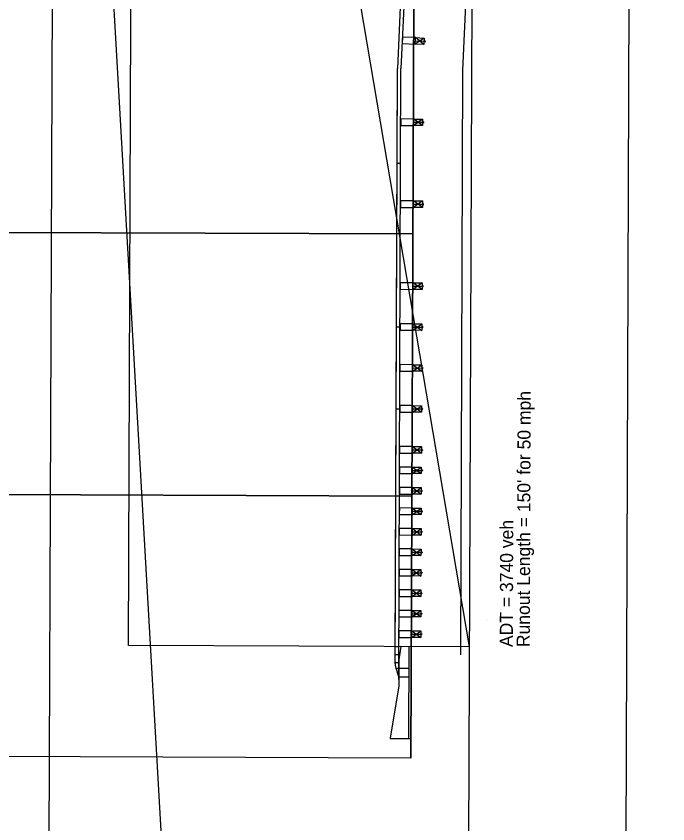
# Model space of a CAD drawing. Extents: x 15359458 to 15360238, y 8797399 to 8799222.
# Drawn here: x 15359925.1 to 15359974.9, y 8798363.3 to 8798425 of the extents above; entities that cross this region are included whole.
import ezdxf

# ---------------------------------------------------------------- set-up
doc = ezdxf.new("R2010")
doc.units = 0
for name, color, linetype in [('_CIVIL_CONSTRUCTION', 7, 'Continuous'), ('Alignment', 7, 'Continuous'), ('MeshTop', 7, 'Continuous'), ('PhoTerrainTriangle', 7, 'Continuous'), ('PhoTerrainVoid', 7, 'Continuous')]:
    doc.layers.add(name, color=color, linetype=linetype)

msp = doc.modelspace()

# ---------------------------------------------------------------- linework, layer by layer
at = {"layer": '_CIVIL_CONSTRUCTION'}
for p, q in [((15359954.472, 8798426.267), (15359954.24, 8798420.983)), ((15359954.742, 8798426.255), (15359954.511, 8798420.98)), ((15359954.616, 8798423.381), (15359954.594, 8798422.881)), ((15359955.616, 8798423.337), (15359954.616, 8798423.381)), ((15359955.594, 8798422.837), (15359955.616, 8798423.337)), ((15359956.282, 8798423.308), (15359955.594, 8798422.837)), ((15359956.26, 8798422.808), (15359955.616, 8798423.337)), ((15359954.594, 8798422.881), (15359955.594, 8798422.837)), ((15359955.605, 8798423.087), (15359956.271, 8798423.058)), ((15359956.368, 8798423.054), (15359956.375, 8798423.053)), ((15359954.213, 8798413.757), (15359954.24, 8798420.983)), ((15359954.484, 8798413.756), (15359954.511, 8798420.98)), ((15359954.497, 8798417.132), (15359954.495, 8798416.631)), ((15359955.498, 8798417.128), (15359954.497, 8798417.132)), ((15359955.496, 8798416.628), (15359955.498, 8798417.128)), ((15359956.164, 8798417.125), (15359955.496, 8798416.628)), ((15359956.162, 8798416.625), (15359955.498, 8798417.128)), ((15359954.495, 8798416.631), (15359955.496, 8798416.628)), ((15359955.497, 8798416.878), (15359956.163, 8798416.875)), ((15359956.26, 8798416.875), (15359956.267, 8798416.875)), ((15359954.069, 8798375.557), (15359954.213, 8798413.757)), ((15359954.213, 8798413.757), (15359954.484, 8798413.756)), ((15359954.213, 8798413.757), (15359954.484, 8798413.756)), ((15359954.335, 8798374.361), (15359954.484, 8798413.756)), ((15359954.473, 8798410.882), (15359954.471, 8798410.381)), ((15359954.471, 8798410.381), (15359955.472, 8798410.378)), ((15359955.474, 8798410.878), (15359954.473, 8798410.882)), ((15359955.472, 8798410.378), (15359955.474, 8798410.878)), ((15359956.141, 8798410.875), (15359955.472, 8798410.378)), ((15359955.473, 8798410.628), (15359956.14, 8798410.625)), ((15359956.139, 8798410.375), (15359955.474, 8798410.878)), ((15359956.237, 8798410.625), (15359956.244, 8798410.625)), ((15359954.449, 8798404.632), (15359954.448, 8798404.131)), ((15359955.45, 8798404.628), (15359954.449, 8798404.632)), ((15359955.448, 8798404.128), (15359955.45, 8798404.628)), ((15359956.117, 8798404.625), (15359955.448, 8798404.128)), ((15359955.449, 8798404.378), (15359956.116, 8798404.375)), ((15359956.115, 8798404.125), (15359955.45, 8798404.628)), ((15359956.213, 8798404.375), (15359956.22, 8798404.375)), ((15359954.448, 8798404.131), (15359955.448, 8798404.128)), ((15359954.069, 8798375.653), (15359954.166, 8798401.257)), ((15359954.166, 8798401.257), (15359954.437, 8798401.256)), ((15359954.438, 8798401.506), (15359954.436, 8798401.007)), ((15359955.437, 8798401.503), (15359954.438, 8798401.506)), ((15359955.435, 8798401.003), (15359955.437, 8798401.503)), ((15359955.435, 8798401.003), (15359956.104, 8798401.5)), ((15359955.436, 8798401.253), (15359956.103, 8798401.25)), ((15359955.437, 8798401.503), (15359956.102, 8798401)), ((15359956.104, 8798401.5), (15359956.102, 8798401)), ((15359956.102, 8798401.17), (15359956.119, 8798401.17)), ((15359956.103, 8798401.33), (15359956.12, 8798401.33)), ((15359956.12, 8798401.33), (15359956.119, 8798401.17)), ((15359956.119, 8798401.29), (15359956.157, 8798401.29)), ((15359956.119, 8798401.274), (15359956.157, 8798401.274)), ((15359956.119, 8798401.226), (15359956.157, 8798401.226)), ((15359956.119, 8798401.21), (15359956.157, 8798401.21)), ((15359956.157, 8798401.29), (15359956.157, 8798401.21)), ((15359956.157, 8798401.26), (15359956.186, 8798401.26)), ((15359956.157, 8798401.24), (15359956.186, 8798401.24)), ((15359956.186, 8798401.26), (15359956.186, 8798401.24)), ((15359954.436, 8798401.007), (15359955.435, 8798401.003)), ((15359954.426, 8798398.381), (15359954.424, 8798397.882)), ((15359955.425, 8798398.378), (15359954.426, 8798398.381)), ((15359955.423, 8798397.878), (15359955.425, 8798398.378)), ((15359955.423, 8798397.878), (15359956.092, 8798398.375)), ((15359955.424, 8798398.128), (15359956.091, 8798398.125)), ((15359955.425, 8798398.378), (15359956.09, 8798397.875)), ((15359956.092, 8798398.375), (15359956.09, 8798397.875)), ((15359956.091, 8798398.205), (15359956.108, 8798398.205)), ((15359956.091, 8798398.045), (15359956.107, 8798398.045)), ((15359956.108, 8798398.205), (15359956.107, 8798398.045)), ((15359956.107, 8798398.101), (15359956.145, 8798398.101)), ((15359956.107, 8798398.085), (15359956.145, 8798398.085)), ((15359956.108, 8798398.165), (15359956.145, 8798398.165)), ((15359956.108, 8798398.149), (15359956.145, 8798398.149)), ((15359956.145, 8798398.165), (15359956.145, 8798398.085)), ((15359956.145, 8798398.135), (15359956.174, 8798398.135)), ((15359956.145, 8798398.115), (15359956.174, 8798398.115)), ((15359956.174, 8798398.135), (15359956.174, 8798398.115)), ((15359954.424, 8798397.882), (15359955.423, 8798397.878)), ((15359954.142, 8798395.008), (15359954.413, 8798395.007)), ((15359954.414, 8798395.257), (15359954.412, 8798394.757)), ((15359955.414, 8798395.253), (15359954.414, 8798395.257)), ((15359955.412, 8798394.753), (15359955.414, 8798395.253)), ((15359955.412, 8798394.753), (15359956.08, 8798395.25)), ((15359955.413, 8798395.003), (15359956.079, 8798395)), ((15359955.414, 8798395.253), (15359956.078, 8798394.75)), ((15359956.08, 8798395.25), (15359956.078, 8798394.75)), ((15359956.079, 8798395.08), (15359956.096, 8798395.08)), ((15359956.079, 8798394.92), (15359956.095, 8798394.92)), ((15359956.096, 8798395.08), (15359956.095, 8798394.92)), ((15359956.096, 8798395.04), (15359956.133, 8798395.04)), ((15359956.096, 8798395.024), (15359956.133, 8798395.024)), ((15359956.096, 8798394.976), (15359956.133, 8798394.976)), ((15359956.096, 8798394.96), (15359956.133, 8798394.96)), ((15359956.133, 8798395.04), (15359956.133, 8798394.96)), ((15359956.133, 8798395.01), (15359956.163, 8798395.01)), ((15359956.133, 8798394.99), (15359956.163, 8798394.99)), ((15359956.163, 8798395.01), (15359956.163, 8798394.99)), ((15359954.412, 8798394.757), (15359955.412, 8798394.753)), ((15359954.402, 8798392.132), (15359954.4, 8798391.632)), ((15359955.402, 8798392.128), (15359954.402, 8798392.132)), ((15359955.4, 8798391.628), (15359955.402, 8798392.128)), ((15359955.4, 8798391.628), (15359956.068, 8798392.125)), ((15359955.401, 8798391.878), (15359956.067, 8798391.875)), ((15359955.402, 8798392.128), (15359956.066, 8798391.625)), ((15359956.068, 8798392.125), (15359956.066, 8798391.625)), ((15359956.068, 8798391.955), (15359956.084, 8798391.955)), ((15359956.084, 8798391.955), (15359956.084, 8798391.795)), ((15359956.084, 8798391.915), (15359956.121, 8798391.915)), ((15359956.084, 8798391.899), (15359956.121, 8798391.899)), ((15359956.084, 8798391.851), (15359956.121, 8798391.851)), ((15359956.084, 8798391.835), (15359956.121, 8798391.835)), ((15359956.121, 8798391.915), (15359956.121, 8798391.835)), ((15359956.121, 8798391.885), (15359956.151, 8798391.885)), ((15359956.121, 8798391.865), (15359956.151, 8798391.865)), ((15359956.151, 8798391.885), (15359956.151, 8798391.865)), ((15359954.4, 8798391.632), (15359955.4, 8798391.628)), ((15359956.067, 8798391.795), (15359956.084, 8798391.795)), ((15359954.396, 8798390.569), (15359954.394, 8798390.069)), ((15359954.394, 8798390.069), (15359955.394, 8798390.066)), ((15359955.396, 8798390.565), (15359954.396, 8798390.569)), ((15359955.394, 8798390.066), (15359955.396, 8798390.565)), ((15359955.394, 8798390.065), (15359956.062, 8798390.563)), ((15359955.395, 8798390.315), (15359956.061, 8798390.313)), ((15359955.396, 8798390.565), (15359956.061, 8798390.063)), ((15359956.062, 8798390.563), (15359956.061, 8798390.063)), ((15359956.061, 8798390.233), (15359956.078, 8798390.233)), ((15359956.062, 8798390.393), (15359956.078, 8798390.393)), ((15359956.078, 8798390.393), (15359956.078, 8798390.233)), ((15359956.078, 8798390.353), (15359956.116, 8798390.353)), ((15359956.078, 8798390.337), (15359956.115, 8798390.337)), ((15359956.078, 8798390.289), (15359956.115, 8798390.289)), ((15359956.078, 8798390.273), (15359956.115, 8798390.273)), ((15359956.116, 8798390.353), (15359956.115, 8798390.273)), ((15359956.115, 8798390.323), (15359956.145, 8798390.322)), ((15359956.115, 8798390.303), (15359956.145, 8798390.302)), ((15359956.145, 8798390.322), (15359956.145, 8798390.302)), ((15359954.39, 8798389.007), (15359954.388, 8798388.507)), ((15359954.39, 8798389.007), (15359954.388, 8798388.507)), ((15359955.39, 8798389.003), (15359954.39, 8798389.007)), ((15359955.39, 8798389.003), (15359954.39, 8798389.007)), ((15359955.388, 8798388.503), (15359955.39, 8798389.003)), ((15359955.388, 8798388.503), (15359955.39, 8798389.003)), ((15359955.388, 8798388.503), (15359956.056, 8798389)), ((15359955.389, 8798388.753), (15359956.056, 8798388.75)), ((15359955.39, 8798389.003), (15359956.055, 8798388.5)), ((15359956.056, 8798389), (15359956.055, 8798388.5)), ((15359956.056, 8798388.83), (15359956.072, 8798388.83)), ((15359956.072, 8798388.83), (15359956.072, 8798388.67)), ((15359956.072, 8798388.79), (15359956.11, 8798388.79)), ((15359956.072, 8798388.774), (15359956.11, 8798388.774)), ((15359956.11, 8798388.79), (15359956.109, 8798388.71)), ((15359956.11, 8798388.76), (15359956.139, 8798388.76)), ((15359956.139, 8798388.76), (15359956.139, 8798388.74)), ((15359954.388, 8798388.507), (15359955.388, 8798388.503)), ((15359954.388, 8798388.507), (15359955.388, 8798388.503)), ((15359956.055, 8798388.67), (15359956.072, 8798388.67)), ((15359956.072, 8798388.726), (15359956.109, 8798388.726)), ((15359956.072, 8798388.71), (15359956.109, 8798388.71)), ((15359956.109, 8798388.74), (15359956.139, 8798388.74)), ((15359954.384, 8798387.444), (15359954.383, 8798386.944)), ((15359954.383, 8798386.944), (15359955.382, 8798386.941)), ((15359955.384, 8798387.44), (15359954.384, 8798387.444)), ((15359955.382, 8798386.941), (15359955.384, 8798387.44)), ((15359955.382, 8798386.94), (15359956.051, 8798387.438)), ((15359955.383, 8798387.19), (15359956.05, 8798387.188)), ((15359955.384, 8798387.44), (15359956.049, 8798386.938)), ((15359956.051, 8798387.438), (15359956.049, 8798386.938)), ((15359956.049, 8798387.108), (15359956.066, 8798387.108)), ((15359956.05, 8798387.268), (15359956.066, 8798387.268)), ((15359956.066, 8798387.268), (15359956.066, 8798387.108)), ((15359956.066, 8798387.228), (15359956.104, 8798387.228)), ((15359956.066, 8798387.212), (15359956.104, 8798387.212)), ((15359956.066, 8798387.164), (15359956.103, 8798387.164)), ((15359956.066, 8798387.148), (15359956.103, 8798387.148)), ((15359956.104, 8798387.228), (15359956.103, 8798387.148)), ((15359956.104, 8798387.198), (15359956.133, 8798387.197)), ((15359956.104, 8798387.178), (15359956.133, 8798387.177)), ((15359956.133, 8798387.197), (15359956.133, 8798387.177)), ((15359954.379, 8798385.882), (15359954.377, 8798385.382)), ((15359955.378, 8798385.878), (15359954.379, 8798385.882)), ((15359955.376, 8798385.378), (15359955.378, 8798385.878)), ((15359955.376, 8798385.378), (15359956.045, 8798385.875)), ((15359955.378, 8798385.878), (15359956.043, 8798385.375)), ((15359956.045, 8798385.875), (15359956.043, 8798385.375)), ((15359956.044, 8798385.705), (15359956.061, 8798385.705)), ((15359956.061, 8798385.705), (15359956.06, 8798385.545)), ((15359954.377, 8798385.382), (15359955.376, 8798385.378)), ((15359955.377, 8798385.628), (15359956.044, 8798385.625)), ((15359956.043, 8798385.545), (15359956.06, 8798385.545)), ((15359956.06, 8798385.665), (15359956.098, 8798385.665)), ((15359956.06, 8798385.649), (15359956.098, 8798385.649)), ((15359956.06, 8798385.601), (15359956.098, 8798385.601)), ((15359956.06, 8798385.585), (15359956.098, 8798385.585)), ((15359956.098, 8798385.665), (15359956.098, 8798385.585)), ((15359956.098, 8798385.635), (15359956.127, 8798385.635)), ((15359956.098, 8798385.615), (15359956.127, 8798385.615)), ((15359956.127, 8798385.635), (15359956.127, 8798385.615)), ((15359954.373, 8798384.319), (15359954.371, 8798383.819)), ((15359955.372, 8798384.315), (15359954.373, 8798384.319)), ((15359955.37, 8798383.816), (15359955.372, 8798384.315)), ((15359955.37, 8798383.815), (15359956.039, 8798384.313)), ((15359955.371, 8798384.065), (15359956.038, 8798384.063)), ((15359955.372, 8798384.315), (15359956.037, 8798383.813)), ((15359956.039, 8798384.313), (15359956.037, 8798383.813)), ((15359956.038, 8798384.143), (15359956.055, 8798384.143)), ((15359956.038, 8798383.983), (15359956.054, 8798383.983)), ((15359956.055, 8798384.143), (15359956.054, 8798383.983)), ((15359956.054, 8798384.087), (15359956.092, 8798384.087)), ((15359956.054, 8798384.039), (15359956.092, 8798384.039)), ((15359956.054, 8798384.023), (15359956.092, 8798384.023)), ((15359956.055, 8798384.103), (15359956.092, 8798384.103)), ((15359956.092, 8798384.103), (15359956.092, 8798384.023)), ((15359956.092, 8798384.073), (15359956.121, 8798384.072)), ((15359956.092, 8798384.053), (15359956.121, 8798384.052)), ((15359956.121, 8798384.072), (15359956.121, 8798384.052)), ((15359954.371, 8798383.819), (15359955.37, 8798383.816)), ((15359954.367, 8798382.757), (15359954.365, 8798382.257)), ((15359955.366, 8798382.753), (15359954.367, 8798382.757)), ((15359955.364, 8798382.253), (15359955.366, 8798382.753)), ((15359955.364, 8798382.253), (15359956.033, 8798382.75)), ((15359955.366, 8798382.753), (15359956.031, 8798382.25)), ((15359956.033, 8798382.75), (15359956.031, 8798382.25)), ((15359954.365, 8798382.257), (15359955.364, 8798382.253)), ((15359955.365, 8798382.503), (15359956.032, 8798382.5)), ((15359956.032, 8798382.58), (15359956.049, 8798382.58)), ((15359956.032, 8798382.42), (15359956.048, 8798382.42)), ((15359956.049, 8798382.58), (15359956.048, 8798382.42)), ((15359956.048, 8798382.476), (15359956.086, 8798382.476)), ((15359956.048, 8798382.46), (15359956.086, 8798382.46)), ((15359956.049, 8798382.54), (15359956.086, 8798382.54)), ((15359956.049, 8798382.524), (15359956.086, 8798382.524)), ((15359956.086, 8798382.54), (15359956.086, 8798382.46)), ((15359956.086, 8798382.51), (15359956.115, 8798382.51)), ((15359956.086, 8798382.49), (15359956.115, 8798382.49)), ((15359956.115, 8798382.51), (15359956.115, 8798382.49)), ((15359954.361, 8798381.194), (15359954.359, 8798380.694)), ((15359955.36, 8798381.19), (15359954.361, 8798381.194)), ((15359955.358, 8798380.691), (15359955.36, 8798381.19)), ((15359955.358, 8798380.69), (15359956.027, 8798381.188)), ((15359955.359, 8798380.94), (15359956.026, 8798380.938)), ((15359955.36, 8798381.19), (15359956.025, 8798380.688)), ((15359956.027, 8798381.188), (15359956.025, 8798380.688)), ((15359956.026, 8798381.018), (15359956.043, 8798381.018)), ((15359956.026, 8798380.858), (15359956.042, 8798380.858)), ((15359956.043, 8798381.018), (15359956.042, 8798380.858)), ((15359956.042, 8798380.914), (15359956.08, 8798380.914)), ((15359956.042, 8798380.898), (15359956.08, 8798380.898)), ((15359956.043, 8798380.978), (15359956.08, 8798380.978)), ((15359956.043, 8798380.962), (15359956.08, 8798380.962)), ((15359956.08, 8798380.978), (15359956.08, 8798380.898)), ((15359956.08, 8798380.948), (15359956.109, 8798380.948)), ((15359956.08, 8798380.928), (15359956.109, 8798380.928)), ((15359956.109, 8798380.948), (15359956.109, 8798380.928)), ((15359954.359, 8798380.694), (15359955.358, 8798380.691)), ((15359954.355, 8798379.632), (15359954.353, 8798379.132)), ((15359955.354, 8798379.628), (15359954.355, 8798379.632)), ((15359955.353, 8798379.128), (15359955.354, 8798379.628)), ((15359955.353, 8798379.128), (15359956.021, 8798379.625)), ((15359955.354, 8798379.628), (15359956.019, 8798379.125)), ((15359956.021, 8798379.625), (15359956.019, 8798379.125)), ((15359954.353, 8798379.132), (15359955.353, 8798379.128)), ((15359955.353, 8798379.378), (15359956.02, 8798379.375)), ((15359956.02, 8798379.455), (15359956.037, 8798379.455)), ((15359956.02, 8798379.295), (15359956.036, 8798379.295)), ((15359956.037, 8798379.455), (15359956.036, 8798379.295)), ((15359956.036, 8798379.335), (15359956.074, 8798379.335)), ((15359956.037, 8798379.415), (15359956.074, 8798379.415)), ((15359956.037, 8798379.399), (15359956.074, 8798379.399)), ((15359956.037, 8798379.351), (15359956.074, 8798379.351)), ((15359956.074, 8798379.415), (15359956.074, 8798379.335)), ((15359956.074, 8798379.385), (15359956.104, 8798379.385)), ((15359956.074, 8798379.365), (15359956.103, 8798379.365)), ((15359956.104, 8798379.385), (15359956.103, 8798379.365)), ((15359954.349, 8798378.069), (15359954.347, 8798377.569)), ((15359955.349, 8798378.065), (15359954.349, 8798378.069)), ((15359955.347, 8798377.566), (15359955.349, 8798378.065)), ((15359955.347, 8798377.565), (15359956.015, 8798378.063)), ((15359955.348, 8798377.815), (15359956.014, 8798377.813)), ((15359955.349, 8798378.065), (15359956.013, 8798377.563)), ((15359956.015, 8798378.063), (15359956.013, 8798377.563)), ((15359956.014, 8798377.893), (15359956.031, 8798377.893)), ((15359956.014, 8798377.733), (15359956.03, 8798377.733)), ((15359956.031, 8798377.893), (15359956.03, 8798377.733)), ((15359956.031, 8798377.853), (15359956.068, 8798377.853)), ((15359956.031, 8798377.837), (15359956.068, 8798377.837)), ((15359956.031, 8798377.789), (15359956.068, 8798377.789)), ((15359956.031, 8798377.773), (15359956.068, 8798377.773)), ((15359956.068, 8798377.853), (15359956.068, 8798377.773)), ((15359956.068, 8798377.823), (15359956.098, 8798377.823)), ((15359956.068, 8798377.803), (15359956.098, 8798377.803)), ((15359956.098, 8798377.823), (15359956.098, 8798377.803)), ((15359954.347, 8798377.569), (15359955.347, 8798377.566)), ((15359954.074, 8798376.862), (15359954.344, 8798376.861)), ((15359954.511, 8798376.86), (15359954.341, 8798375.861)), ((15359955.303, 8798376.857), (15359954.511, 8798376.86)), ((15359955.11, 8798369.858), (15359955.136, 8798376.858)), ((15359955.276, 8798369.857), (15359955.303, 8798376.857)), ((15359954.071, 8798376.258), (15359954.342, 8798376.257)), ((15359954.341, 8798375.861), (15359954.333, 8798373.863)), ((15359954.069, 8798375.653), (15359954.34, 8798375.652)), ((15359955.13, 8798375.191), (15359954.127, 8798375.195)), ((15359954.16, 8798375.095), (15359954.215, 8798374.952)), ((15359954.31, 8798374.611), (15359954.309, 8798374.361)), ((15359955.127, 8798374.525), (15359954.309, 8798374.528)), ((15359954.335, 8798374.361), (15359954.309, 8798374.361)), ((15359954.333, 8798373.863), (15359953.693, 8798369.867)), ((15359953.693, 8798369.867), (15359953.693, 8798369.863)), ((15359953.693, 8798369.863), (15359955.276, 8798369.857))]:
    msp.add_line(p, q, dxfattribs=at)
for points in [[(15359955.594, 8798422.837), (15359955.616, 8798423.337), (15359956.282, 8798423.308), (15359956.26, 8798422.808)], [(15359955.496, 8798416.628), (15359955.498, 8798417.128), (15359956.164, 8798417.125), (15359956.162, 8798416.625)], [(15359955.472, 8798410.378), (15359955.474, 8798410.878), (15359956.141, 8798410.875), (15359956.139, 8798410.375)], [(15359955.448, 8798404.128), (15359955.45, 8798404.628), (15359956.117, 8798404.625), (15359956.115, 8798404.125)], [(15359955.435, 8798401.003), (15359955.437, 8798401.503), (15359956.104, 8798401.5), (15359956.102, 8798401)], [(15359955.423, 8798397.878), (15359955.425, 8798398.378), (15359956.092, 8798398.375), (15359956.09, 8798397.875)], [(15359955.412, 8798394.753), (15359955.414, 8798395.253), (15359956.08, 8798395.25), (15359956.078, 8798394.75)], [(15359955.4, 8798391.628), (15359955.402, 8798392.128), (15359956.068, 8798392.125), (15359956.066, 8798391.625)], [(15359955.394, 8798390.065), (15359955.396, 8798390.565), (15359956.062, 8798390.563), (15359956.061, 8798390.063)], [(15359955.388, 8798388.503), (15359955.39, 8798389.003), (15359956.056, 8798389), (15359956.055, 8798388.5)], [(15359955.382, 8798386.94), (15359955.384, 8798387.44), (15359956.051, 8798387.438), (15359956.049, 8798386.938)], [(15359955.376, 8798385.378), (15359955.378, 8798385.878), (15359956.045, 8798385.875), (15359956.043, 8798385.375)], [(15359955.37, 8798383.815), (15359955.372, 8798384.315), (15359956.039, 8798384.313), (15359956.037, 8798383.813)], [(15359955.364, 8798382.253), (15359955.366, 8798382.753), (15359956.033, 8798382.75), (15359956.031, 8798382.25)], [(15359955.358, 8798380.69), (15359955.36, 8798381.19), (15359956.027, 8798381.188), (15359956.025, 8798380.688)], [(15359955.353, 8798379.128), (15359955.354, 8798379.628), (15359956.021, 8798379.625), (15359956.019, 8798379.125)], [(15359955.347, 8798377.565), (15359955.349, 8798378.065), (15359956.015, 8798378.063), (15359956.013, 8798377.563)]]:
    msp.add_lwpolyline(points, close=True, dxfattribs=at)
for points in [[(15359956.27, 8798423.025), (15359956.313, 8798423.023), (15359956.316, 8798423.089), (15359956.273, 8798423.091)], [(15359956.313, 8798423.037), (15359956.368, 8798423.034), (15359956.369, 8798423.073), (15359956.315, 8798423.076)], [(15359956.163, 8798416.842), (15359956.206, 8798416.842), (15359956.206, 8798416.908), (15359956.163, 8798416.908)], [(15359956.206, 8798416.855), (15359956.26, 8798416.855), (15359956.261, 8798416.894), (15359956.206, 8798416.894)], [(15359956.139, 8798410.592), (15359956.183, 8798410.592), (15359956.183, 8798410.658), (15359956.14, 8798410.658)], [(15359956.183, 8798410.605), (15359956.237, 8798410.605), (15359956.237, 8798410.644), (15359956.183, 8798410.644)], [(15359956.116, 8798404.342), (15359956.159, 8798404.342), (15359956.159, 8798404.408), (15359956.116, 8798404.408)], [(15359956.159, 8798404.356), (15359956.213, 8798404.355), (15359956.213, 8798404.394), (15359956.159, 8798404.394)]]:
    msp.add_lwpolyline(points, dxfattribs=at)
for centre, major_axis, start_param, end_param in [((15359955.564, 8798375.631), (-0.006, -1.542), 4.763936, 5.071137), ((15359952.986, 8798374.404), (0.005, 1.379), 4.866664, 5.124351)]:
    msp.add_ellipse(centre, major_axis=major_axis, ratio=0.97085, start_param=start_param, end_param=end_param, dxfattribs=at)
at = {"layer": 'Alignment'}
for p, q in [((15359962.874, 8799211.335), (15359957.014, 8797661.346)), ((15359974.874, 8799211.289), (15359969.014, 8797661.3)), ((15359961.094, 8798378.835), (15359961.094, 8798378.835))]:
    msp.add_line(p, q, dxfattribs=at)
msp.add_lwpolyline([(15359933.719, 8798376.939), (15359934.286, 8798526.938), (15359959.719, 8798376.841)], close=True, dxfattribs=at)
at = {"layer": 'MeshTop'}
for p, q in [((15359959.24, 8798420.864), (15359961.552, 8798473.67)), ((15359954.071, 8798376.258), (15359954.24, 8798420.983)), ((15359959.071, 8798376.239), (15359959.24, 8798420.864))]:
    msp.add_line(p, q, dxfattribs=at)
at = {"layer": 'PhoTerrainTriangle'}
for p, q in [((15359925.969, 8797914.04), (15359928.192, 8798502.036)), ((15359928.192, 8798502.036), (15359961.969, 8797913.904))]:
    msp.add_line(p, q, dxfattribs=at)
at = {"layer": 'PhoTerrainVoid'}
for p, q in [((15359955.27, 8798368.357), (15359955.535, 8798438.357)), ((15359955.535, 8798438.357), (15359955.27, 8798368.357)), ((15359955.535, 8798438.357), (15359955.27, 8798368.357)), ((15359912.255, 8798408.52), (15359955.421, 8798408.357)), ((15359955.421, 8798408.357), (15359912.255, 8798408.52)), ((15359912.18, 8798388.52), (15359955.346, 8798388.357)), ((15359955.346, 8798388.357), (15359912.18, 8798388.52)), ((15359955.27, 8798368.357), (15359912.104, 8798368.521))]:
    msp.add_line(p, q, dxfattribs=at)

# ---------------------------------------------------------------- texts
at = {"layer": 'Alignment'}
for s, p in [("Runout Length = 150' for 50 mph", (15359964.338, 8798376.823)), ('ADT = 3740 veh', (15359963.044, 8798376.828))]:
    msp.add_text(s, height=1, rotation=89.7834, dxfattribs=at).set_placement(p)

doc.saveas('drawing.dxf')
